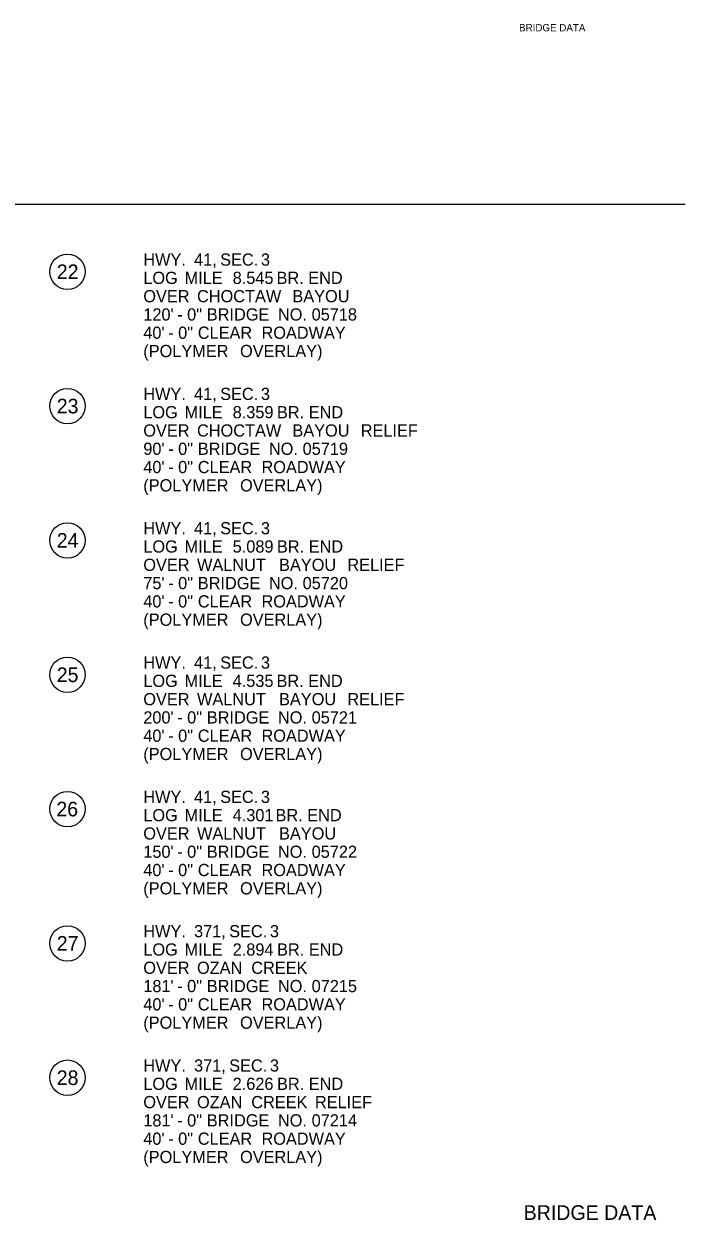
# Model space of a CAD drawing. Extents: x 1930546 to 1934225, y 596452 to 599536.
# Drawn here: x 1931599 to 1932142, y 598531 to 599512 of the extents above; entities that cross this region are included whole.
import ezdxf

# ---------------------------------------------------------------- set-up
doc = ezdxf.new("R2010")
doc.units = 0
for name, color, linetype in [('Default', 7, 'Continuous'), ('R_Border', 7, 'Continuous'), ('R_Border Prem', 7, 'Continuous')]:
    doc.layers.add(name, color=color, linetype=linetype)

msp = doc.modelspace()

# ---------------------------------------------------------------- linework, layer by layer
at = {"layer": 'R_Border'}
msp.add_line((1932141.6, 599363.54), (1930546.24, 599363.54), dxfattribs=at)
for centre in [(1931635.13, 599308.41), (1931635.13, 599198.23), (1931635.13, 599088.06), (1931635.13, 598977.88), (1931635.13, 598867.71), (1931635.13, 598757.53), (1931635.13, 598647.36)]:
    msp.add_circle(centre, 14.52, dxfattribs=at)

# ---------------------------------------------------------------- texts
at = {"layer": 'Default'}
for s, p in [('HWY.', (1931697.34, 599313.41)), (' 41,', (1931735.25, 599313.41)), (' SEC.', (1931756.66, 599313.41)), (' 3', (1931790.07, 599313.41)), ('LOG', (1931697.34, 599298.41)), (' MILE', (1931727.47, 599298.41)), (' 8.545', (1931766.91, 599298.41)), (' BR.', (1931802.87, 599298.41)), (' END', (1931828.9, 599298.41)), ('OVER', (1931697.34, 599283.41)), (' CHOCTAW', (1931737.67, 599283.41)), (' BAYOU', (1931815.89, 599283.41)), ("120'", (1931697.34, 599268.41)), (' 0"', (1931729.57, 599268.41)), (' BRIDGE', (1931745.7, 599268.41)), (' NO.', (1931804.02, 599268.41)), (' 05718', (1931831.68, 599268.41)), (' -', (1931721.54, 599268.41)), ("40'", (1931697.34, 599253.41)), (' -', (1931714.16, 599253.41)), (' 0"', (1931722.18, 599253.41)), (' CLEAR', (1931738.32, 599253.41)), (' ROADWAY', (1931790.54, 599253.41)), ('(POLYMER', (1931697.34, 599238.41)), (' OVERLAY)', (1931772.95, 599238.41)), ('HWY.', (1931697.34, 599203.23)), (' 41,', (1931735.25, 599203.23)), (' SEC.', (1931756.66, 599203.23)), (' 3', (1931790.07, 599203.23)), ('LOG', (1931697.34, 599188.23)), (' MILE', (1931727.47, 599188.23)), (' 8.359', (1931766.91, 599188.23)), (' BR.', (1931803.21, 599188.23)), (' END', (1931829.24, 599188.23)), ('OVER', (1931697.34, 599173.23)), (' CHOCTAW', (1931737.67, 599173.23)), (' BAYOU', (1931815.89, 599173.23)), (' RELIEF', (1931871.91, 599173.23)), ("90'", (1931697.34, 599158.23)), (' 0"', (1931722.18, 599158.23)), (' BRIDGE', (1931738.32, 599158.23)), (' NO.', (1931796.63, 599158.23)), (' 05719', (1931824.29, 599158.23)), (' -', (1931714.16, 599158.23)), ("40'", (1931697.34, 599143.23)), (' -', (1931714.16, 599143.23)), (' 0"', (1931722.18, 599143.23)), (' CLEAR', (1931738.32, 599143.23)), (' ROADWAY', (1931790.54, 599143.23)), ('(POLYMER', (1931697.34, 599128.23)), (' OVERLAY)', (1931772.95, 599128.23)), ('HWY.', (1931697.34, 599093.06)), (' 41,', (1931735.25, 599093.06)), (' SEC.', (1931756.66, 599093.06)), (' 3', (1931790.07, 599093.06)), ('LOG', (1931697.34, 599078.06)), (' MILE', (1931727.47, 599078.06)), (' 5.089', (1931766.91, 599078.06)), (' BR.', (1931803.21, 599078.06)), (' END', (1931829.24, 599078.06)), ('OVER', (1931697.34, 599063.06)), (' WALNUT', (1931737.67, 599063.06)), (' BAYOU', (1931804.95, 599063.06)), (' RELIEF', (1931860.97, 599063.06)), ("75'", (1931697.34, 599048.06)), (' -', (1931714.16, 599048.06)), (' 0"', (1931722.18, 599048.06)), (' BRIDGE', (1931738.32, 599048.06)), (' NO.', (1931796.63, 599048.06)), (' 05720', (1931824.29, 599048.06)), ("40'", (1931697.34, 599033.06)), (' 0"', (1931722.18, 599033.06)), (' CLEAR', (1931738.32, 599033.06)), (' ROADWAY', (1931790.54, 599033.06)), (' -', (1931714.16, 599033.06)), ('(POLYMER', (1931697.34, 599018.06)), (' OVERLAY)', (1931772.95, 599018.06)), ('HWY.', (1931697.34, 598982.88)), (' 41,', (1931735.25, 598982.88)), (' SEC.', (1931756.66, 598982.88)), (' 3', (1931790.07, 598982.88)), ('LOG', (1931697.34, 598967.88)), (' MILE', (1931727.47, 598967.88)), (' 4.535', (1931766.91, 598967.88)), (' BR.', (1931802.87, 598967.88)), (' END', (1931828.9, 598967.88)), ('OVER', (1931697.34, 598952.88)), (' WALNUT', (1931737.67, 598952.88)), (' BAYOU', (1931804.95, 598952.88)), (' RELIEF', (1931860.97, 598952.88)), ("200'", (1931697.34, 598937.88)), (' -', (1931721.54, 598937.88)), (' 0"', (1931729.57, 598937.88)), (' BRIDGE', (1931745.7, 598937.88)), (' NO.', (1931804.02, 598937.88)), (' 05721', (1931831.68, 598937.88)), ("40'", (1931697.34, 598922.88)), (' 0"', (1931722.18, 598922.88)), (' CLEAR', (1931738.32, 598922.88)), (' ROADWAY', (1931790.54, 598922.88)), (' -', (1931714.16, 598922.88)), ('(POLYMER', (1931697.34, 598907.88)), (' OVERLAY)', (1931772.95, 598907.88)), ('HWY.', (1931697.34, 598872.71)), (' 41,', (1931735.25, 598872.71)), (' SEC.', (1931756.66, 598872.71)), (' 3', (1931790.07, 598872.71)), ('LOG', (1931697.34, 598857.71)), (' MILE', (1931727.47, 598857.71)), (' 4.301', (1931766.91, 598857.71)), (' BR.', (1931802.03, 598857.71)), (' END', (1931828.06, 598857.71)), ('OVER', (1931697.34, 598842.71)), (' WALNUT', (1931737.67, 598842.71)), (' BAYOU', (1931804.95, 598842.71)), ("150'", (1931697.34, 598827.71)), (' 0"', (1931729.57, 598827.71)), (' BRIDGE', (1931745.7, 598827.71)), (' NO.', (1931804.02, 598827.71)), (' 05722', (1931831.68, 598827.71)), ("40'", (1931697.34, 598812.71)), (' -', (1931721.54, 598827.71)), (' 0"', (1931722.18, 598812.71)), (' CLEAR', (1931738.32, 598812.71)), (' ROADWAY', (1931790.54, 598812.71)), (' -', (1931714.16, 598812.71)), ('(POLYMER', (1931697.34, 598797.71)), (' OVERLAY)', (1931772.95, 598797.71)), ('HWY.', (1931697.34, 598762.53)), (' 371,', (1931735.25, 598762.53)), (' SEC.', (1931764.04, 598762.53)), (' 3', (1931797.45, 598762.53)), ('LOG', (1931697.34, 598747.53)), (' MILE', (1931727.47, 598747.53)), (' 2.894', (1931766.91, 598747.53)), (' BR.', (1931803.33, 598747.53)), (' END', (1931829.36, 598747.53)), ('OVER', (1931697.34, 598732.53)), (' OZAN', (1931737.67, 598732.53)), (' CREEK', (1931782.15, 598732.53)), ("181'", (1931697.34, 598717.53)), (' 0"', (1931729.57, 598717.53)), (' BRIDGE', (1931745.7, 598717.53)), (' NO.', (1931804.02, 598717.53)), (' 07215', (1931831.68, 598717.53)), (' -', (1931721.54, 598717.53)), ("40'", (1931697.34, 598702.53)), (' -', (1931714.16, 598702.53)), (' 0"', (1931722.18, 598702.53)), (' CLEAR', (1931738.32, 598702.53)), (' ROADWAY', (1931790.54, 598702.53)), ('(POLYMER', (1931697.34, 598687.53)), (' OVERLAY)', (1931772.95, 598687.53)), ('HWY.', (1931697.34, 598652.36)), (' 371,', (1931735.25, 598652.36)), (' SEC.', (1931764.04, 598652.36)), (' 3', (1931797.45, 598652.36)), ('LOG', (1931697.34, 598637.36)), (' MILE', (1931727.47, 598637.36)), (' 2.626', (1931766.91, 598637.36)), (' BR.', (1931803.28, 598637.36)), (' END', (1931829.31, 598637.36)), ('OVER', (1931697.34, 598622.36)), (' OZAN', (1931737.67, 598622.36)), (' CREEK', (1931782.15, 598622.36)), (' RELIEF', (1931834.36, 598622.36)), ("181'", (1931697.34, 598607.36)), (' 0"', (1931729.57, 598607.36)), (' BRIDGE', (1931745.7, 598607.36)), (' NO.', (1931804.02, 598607.36)), (' 07214', (1931831.68, 598607.36)), (' -', (1931721.54, 598607.36)), ("40'", (1931697.34, 598592.36)), (' 0"', (1931722.18, 598592.36)), (' CLEAR', (1931738.32, 598592.36)), (' ROADWAY', (1931790.54, 598592.36)), ('(POLYMER', (1931697.34, 598577.36)), (' -', (1931714.16, 598592.36)), (' OVERLAY)', (1931772.95, 598577.36))]:
    msp.add_text(s, height=10, rotation=360, dxfattribs=at).set_placement(p)
at = {"layer": 'R_Border'}
for s, p in [('22', (1931626.34, 599302.41)), ('23', (1931626.34, 599192.23)), ('24', (1931626.34, 599082.06)), ('25', (1931626.34, 598971.88)), ('26', (1931626.01, 598861.71)), ('27', (1931626.34, 598751.53)), ('28', (1931626.34, 598641.36)), ('BRIDGE DATA', (1932009.26, 598530.75))]:
    msp.add_text(s, height=12, rotation=360, dxfattribs=at).set_placement(p)
at = {"layer": 'R_Border Prem'}
msp.add_text('BRIDGE DATA', height=6, rotation=360, dxfattribs=at).set_placement((1932005.48, 599505.6))

doc.saveas('drawing.dxf')
